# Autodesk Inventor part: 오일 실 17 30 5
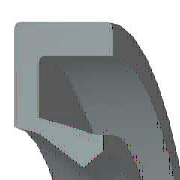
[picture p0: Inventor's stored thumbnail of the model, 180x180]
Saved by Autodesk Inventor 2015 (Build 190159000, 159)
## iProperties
IsCustomPart: 1
Created: 2012-02
Part Number: 오일 실 17 30 5
Material: 고무
Description: 오일 실 - 비스프링, 조립 GA
Document SubType Name: Modeling
Standard: JIS B 2402
Designer: mduedu
Standards Organization: JIS
Language: ko-KR
Size Designation: 17 30 5 A
Categories: <MemberInstance><Categories><Category DisplayName="샤프트 부품" InternalName="7f7aeb1f-a693-4053-b835-cee3144e0d98" Mnemonic="SHFT"><Category DisplayName="실링" Intern
Density: 0.93 g/cm^3
Appearance: Rubber-Black
Author: mduedu
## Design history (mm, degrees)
body "Solid1"
revolve "회전1" stored, may be unused: angle "d27" = 360 deg
fillet "모깎기1" dims "d28" = 0.25 (= 0.05 x b)
sketch "스케치2"
  geometry: L1 (10.636, -3.75)-(11.286, -5); L2 (9.769, -3.438)-(10.636, -3.75); L3 (8.5, -1.375)-(9.769, -3.438); L4 (9.5, -0.75)-(8.5, -1.375); L5 (12.4, -4.375)-(9.5, -0.75); L6 (12.4, -0.25)-(12.4, -4.375); L7 (13.7, -0.25)-(12.4, -0.25); L8 (13.7, 0)-(13.7, -0.25); L9 (15, 0)-(13.7, 0); L10 (15, -5)-(15, 0); L11 (11.286, -5)-(15, -5); L12 (0, -9.6)-(0, 1.6) reference; L13 (28, 0)-(14, 0) reference
  constraints: 22 end point, 3 horizontal, 3 vertical
  dimensions: "d2" = 5 distance of L10.start L9.start (= b); "d4" = 1.3 distance of L9.start L8.start (= 0.1 x dd - 0.1 x Diam); "d6" = 0.25 distance of L8.start L7.start (= 0.05 x b); "d8" = 1 horizontal distance of L4.start L3.start (= 0.0769231 x dd - 0.0769231 x Diam); "d10" = 0.625 vertical distance of L5.start L10.start (= 0.125 x b); "d12" = 1.3 distance of L7.start L6.start (= 0.1 x dd - 0.1 x Diam); "d14" = 0.5 vertical distance of L4.start L6.start (= 0.1 x b); "d16" = 3.71429 distance of L1.end L10.start (= 0.285714 x dd - 0.285714 x Diam); "d18" = 0.65 horizontal distance of L1.start L1.end (= 0.05 x dd - 0.05 x Diam); "d20" = 0.625 vertical distance of L4.start L3.start (= 0.125 x b); "d22" = 1.25 vertical distance of L1.start L1.end (= 0.25 x b); "d24" = 0.86667 horizontal distance of L2.start L1.start (= 0.0666667 x dd - 0.0666667 x Diam); "d26" = 0.3125 vertical distance of L2.start L1.start (= 0.0625 x b); "d29" = 0 distance between parallel lines of L13 L9; "d30" = 8.5 distance from line of L3.start L12 (= 0.5 x Diam); "d31" = 15 distance between parallel lines of L12 L10 (= 0.5 x dd)
other parameters: "Diam" = 17 [user parameter; used in 7 equation terms], "b" = 5 [user parameter; used in 8 equation terms], "d1" = 8 (derived), "d3" = 2 (derived), "d5" = 0.4 (derived), "d7" = 1.53846 (derived), "d9" = 1 (derived), "d11" = 2 (derived), "d13" = 0.8 (derived), "d15" = 5.71429 (derived), "d17" = 1 (derived), "d19" = 1 (derived), "d21" = 2 (derived), "d23" = 1.33333 (derived), "d25" = 0.5 (derived), "d32" = 0
